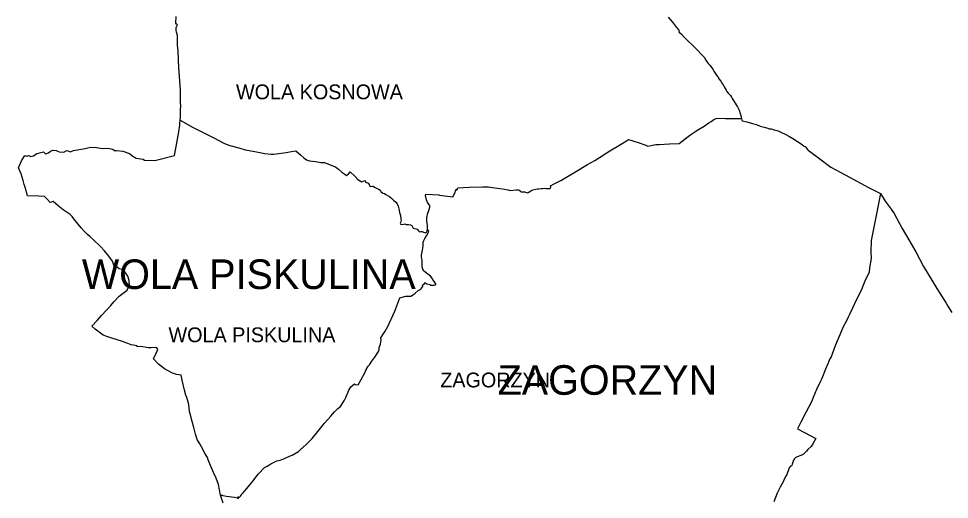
# Model space of a CAD drawing. Extents: x -562952 to -547638, y 190691 to 208158.
# Drawn here: x -562952 to -557283, y 202309 to 205234 of the extents above; entities that cross this region are included whole.
import ezdxf

# ---------------------------------------------------------------- set-up
doc = ezdxf.new("R2010")
doc.units = 0
for name, color, linetype in [('granica_gminy', 7, 'Continuous'), ('granica_sołectwa', 7, 'Continuous'), ('nazwy miejscowości', 7, 'Continuous'), ('nazwy miejscowości DUŻE', 7, 'Continuous'), ('obwódka', 7, 'Continuous')]:
    doc.layers.add(name, color=color, linetype=linetype)

msp = doc.modelspace()

# ---------------------------------------------------------------- linework, layer by layer
at = {"layer": 'granica_gminy'}
msp.add_lwpolyline([(-561705.3, 202285), (-561722.3, 202335.3), (-561733.8, 202399.5), (-561749, 202437.6), (-561764.1, 202472.4), (-561782.1, 202515.8), (-561796.6, 202549.2), (-561802.2, 202563.4), (-561815, 202586.5), (-561838, 202627.6), (-561848.7, 202645.8), (-561863.9, 202672.8), (-561873.8, 202706), (-561884.1, 202745.5), (-561894.5, 202783), (-561905.1, 202820.9), (-561911.2, 202843.6), (-561915, 202885.4), (-561927.8, 202927.9), (-561933.8, 202942.5), (-561940.7, 202972.5), (-561954.8, 203034.6), (-561961.9, 203063.8), (-561989.8, 203068.2), (-562015, 203075.6), (-562063.8, 203102.5), (-562099.8, 203130.4), (-562130.2, 203162.8), (-562113.1, 203199.1), (-562103, 203219.9), (-562109.4, 203229.8), (-562118.6, 203232.3), (-562143.8, 203230.8), (-562160.4, 203231.3), (-562206.5, 203238.1), (-562228.8, 203236.9), (-562230.3, 203241.9), (-562266.8, 203248.5), (-562287.5, 203257.4), (-562318.7, 203269.6), (-562383.2, 203288.8), (-562414.9, 203299.2), (-562436.4, 203307.1), (-562484.8, 203344.9), (-562504.9, 203362.5), (-562473.2, 203397.3), (-562446, 203427.7), (-562414.9, 203462.1), (-562390.6, 203488.6), (-562371.3, 203510.4), (-562340.2, 203545), (-562291, 203581.6), (-562276.9, 203611.7), (-562277.6, 203634.7), (-562279.3, 203639.9), (-562285.8, 203666.8), (-562299.9, 203688), (-562308.5, 203698.9), (-562313.1, 203702.6), (-562321.8, 203706.8), (-562338.9, 203712), (-562351.2, 203721.7), (-562370, 203728.4), (-562380.2, 203759), (-562402.2, 203787.7), (-562428.3, 203820.4), (-562454.3, 203849.9), (-562493.8, 203885.7), (-562515.5, 203905.7), (-562531.9, 203920.1), (-562554.3, 203943.2), (-562571.4, 203960.6), (-562606.7, 204005), (-562622.3, 204024.1), (-562625, 204030), (-562638.1, 204041.3), (-562679.8, 204070), (-562710.8, 204095.5), (-562740.6, 204120.2), (-562758.7, 204114.3), (-562778.9, 204135.3), (-562793.5, 204152), (-562827.9, 204153.8), (-562898.1, 204156.5), (-562911.5, 204208.4), (-562918.2, 204225), (-562924.6, 204248), (-562936.7, 204289.2), (-562951.8, 204325.3), (-562934, 204369), (-562913, 204399.9), (-562908.5, 204399.7), (-562899.1, 204396.5), (-562892.5, 204401.2), (-562884, 204398.4), (-562878.1, 204394.2), (-562861.3, 204399.2), (-562839.9, 204414), (-562833.5, 204415.3), (-562800.1, 204422.4), (-562794.9, 204417), (-562787.9, 204410.3), (-562769.2, 204417), (-562758.6, 204428.1), (-562740.5, 204433.6), (-562723, 204432.3), (-562703.9, 204423.2), (-562676.1, 204421.2), (-562659, 204430.4), (-562636, 204422.2), (-562617.5, 204431.1), (-562546.1, 204442.7), (-562522.6, 204450.4), (-562490, 204450.7), (-562441.8, 204444), (-562408.7, 204444.5), (-562377.3, 204439), (-562367.4, 204431.4), (-562356.3, 204430.4), (-562316.7, 204427.4), (-562277.2, 204414), (-562263.8, 204403.1), (-562255.2, 204396.5), (-562236.4, 204385.6), (-562192.8, 204378.2), (-562184.9, 204373.2), (-562122.1, 204369.5), (-562001.4, 204400.2), (-561992.5, 204456.5), (-561976.1, 204544.6), (-561970.5, 204585.8), (-561969.7, 204596.2), (-561967.1, 204615.2), (-561965.7, 204630.7), (-561965.9, 204679.8), (-561964.8, 204700.1), (-561965.6, 204724.1), (-561965.9, 204744.5), (-561965.6, 204800.7), (-561976.8, 204934.1), (-561981, 205035.6), (-561983.2, 205071.8), (-561983.8, 205131.9), (-561989.2, 205151.8), (-561992, 205164.3), (-561991.4, 205179.4), (-561984.5, 205196.8), (-561990.5, 205200.1), (-561995, 205205.5), (-561993.1, 205247.4)], dxfattribs=at)
at = {"layer": 'granica_sołectwa'}
for p, q in [((-559285.8, 204468.2), (-559248.5, 204490.9)), ((-559248.5, 204490.9), (-559236.3, 204498.3)), ((-559236.3, 204498.3), (-559179.2, 204479.4)), ((-558929, 204474.6), (-558874.4, 204515.5)), ((-558874.4, 204515.5), (-558857.9, 204527.9)), ((-559442.9, 204371.2), (-559351, 204428.3)), ((-559351, 204428.3), (-559285.8, 204468.2)), ((-559179.2, 204479.4), (-559132.2, 204463.1)), ((-559132.2, 204463.1), (-559118.7, 204458.6)), ((-559118.7, 204458.6), (-559070.5, 204466.9)), ((-559070.5, 204466.9), (-559050.8, 204468.5)), ((-559050.8, 204468.5), (-558986.5, 204471.7)), ((-558986.5, 204471.7), (-558929, 204474.6)), ((-559486.4, 204345.9), (-559442.9, 204371.2)), ((-559565, 204299.3), (-559486.4, 204345.9)), ((-559648.7, 204249.4), (-559565, 204299.3)), ((-560281.4, 204192.5), (-560277, 204204.3)), ((-560277, 204204.3), (-560242.8, 204205.8)), ((-560125.9, 204210.4), (-560090.7, 204210.7)), ((-560090.7, 204210.7), (-560064.9, 204206.3)), ((-560064.9, 204206.3), (-560004, 204198)), ((-560004, 204198), (-559969.5, 204192.4)), ((-559801.9, 204196.5), (-559792, 204197.8)), ((-559792, 204197.8), (-559783.3, 204198.2)), ((-559783.3, 204198.2), (-559769.5, 204200.7)), ((-559769.5, 204200.7), (-559761, 204200.6)), ((-559761, 204200.6), (-559748.6, 204201.3)), ((-559748.6, 204201.3), (-559739, 204200.8)), ((-559724, 204199.5), (-559715.5, 204200.2)), ((-559711.8, 204216), (-559689.6, 204228)), ((-559710.6, 204210.7), (-559711.8, 204216)), ((-559689.6, 204228), (-559648.7, 204249.4)), ((-560473.3, 204157.3), (-560471.1, 204164.7)), ((-560467.3, 204131.2), (-560473.3, 204157.3)), ((-560471.1, 204164.7), (-560392.9, 204161.9)), ((-560307.5, 204148.6), (-560297.5, 204167.6)), ((-560297.5, 204167.6), (-560286.7, 204195.6)), ((-560286.7, 204195.6), (-560281.4, 204192.5)), ((-559969.5, 204192.4), (-559962.4, 204187.6)), ((-559962.4, 204187.6), (-559918.4, 204192.3)), ((-559918.4, 204192.3), (-559906.5, 204192.5)), ((-559906.5, 204192.5), (-559899.6, 204189.4)), ((-559899.6, 204189.4), (-559900, 204183.5)), ((-559900, 204183.5), (-559890.9, 204180.2)), ((-559890.9, 204180.2), (-559878, 204180.3)), ((-559878, 204180.3), (-559870.6, 204179.4)), ((-559870.6, 204179.4), (-559852.2, 204173.8)), ((-559852.2, 204173.8), (-559847.4, 204174.9)), ((-559847.4, 204174.9), (-559832.2, 204185.9)), ((-559832.2, 204185.9), (-559819.2, 204191.4)), ((-559819.2, 204191.4), (-559801.9, 204196.5)), ((-557703, 204169.3), (-557727.2, 204045.3)), ((-560464.4, 204120.4), (-560467.3, 204131.2)), ((-560462.9, 204116.8), (-560464.4, 204120.4)), ((-560459.6, 204112), (-560462.9, 204116.8)), ((-560455.4, 204107.7), (-560459.6, 204112)), ((-560450.5, 204101.1), (-560455.4, 204107.7)), ((-560447.7, 204096.1), (-560450.5, 204101.1)), ((-560450.4, 204071.9), (-560446.4, 204086.1)), ((-560446.4, 204090.6), (-560447.7, 204096.1)), ((-560446.4, 204086.1), (-560446.4, 204090.6)), ((-560465.8, 204023.5), (-560464.4, 204032.3)), ((-560464.4, 204032.3), (-560461.1, 204044.9)), ((-560461.1, 204044.9), (-560459.9, 204050.4)), ((-560459.9, 204050.4), (-560454.6, 204059.4)), ((-560454.6, 204059.4), (-560450.4, 204071.9)), ((-560465.8, 204015.9), (-560465.8, 204023.5)), ((-560465.1, 204003.5), (-560465.8, 204015.9)), ((-560464.4, 203989.6), (-560465.1, 204003.5)), ((-560462.4, 203975.8), (-560464.4, 203989.6)), ((-560461, 203961.8), (-560462.4, 203975.8)), ((-560462.4, 203949.9), (-560461, 203961.8)), ((-560493, 203758.4), (-560494.4, 203764.8)), ((-560493.6, 203741.5), (-560493, 203758.4)), ((-560493.6, 203724.2), (-560493.6, 203741.5)), ((-560489.1, 203709.2), (-560493.6, 203724.2)), ((-560483.5, 203699.8), (-560489.1, 203709.2)), ((-560477.3, 203693.3), (-560483.5, 203699.8)), ((-560459.1, 203678.4), (-560477.3, 203693.3)), ((-560443.8, 203666), (-560459.1, 203678.4)), ((-560434.4, 203657.2), (-560443.8, 203666)), ((-560424.3, 203640.7), (-560434.4, 203657.2)), ((-560409, 203616.3), (-560424.3, 203640.7)), ((-560537.2, 203564.2), (-560517.7, 203578.8)), ((-560517.7, 203578.8), (-560501.4, 203588)), ((-560501.4, 203588), (-560490.7, 203604.6)), ((-560491.7, 203612.4), (-560479.9, 203622.8)), ((-560490.7, 203604.6), (-560491.7, 203612.4)), ((-560479.9, 203622.8), (-560476.7, 203628)), ((-560476.7, 203628), (-560465, 203620.9)), ((-560465, 203620.9), (-560447.7, 203615.7)), ((-560447.7, 203615.7), (-560440.5, 203611.1)), ((-560440.5, 203611.1), (-560421.3, 203611.1)), ((-560421.3, 203611.1), (-560409, 203616.3)), ((-560661.2, 203453.2), (-560630.3, 203534.7)), ((-560630.3, 203534.7), (-560593.8, 203544.4)), ((-560593.8, 203544.4), (-560562.6, 203545)), ((-560562.6, 203545), (-560546.7, 203554.4)), ((-560546.7, 203554.4), (-560537.2, 203564.2)), ((-560703.2, 203359.9), (-560661.2, 203453.2)), ((-560718.7, 203332.7), (-560703.2, 203359.9)), ((-560746.4, 203292), (-560737, 203303.4)), ((-560743.5, 203277.7), (-560746.4, 203292)), ((-560737, 203303.4), (-560732.1, 203314.8)), ((-560732.1, 203314.8), (-560718.7, 203332.7)), ((-560755.8, 203232.4), (-560751.6, 203243.5)), ((-560751.6, 203243.5), (-560748.7, 203252.6)), ((-560748.7, 203252.6), (-560743.5, 203277.7)), ((-560782.2, 203173.3), (-560759.4, 203208.1)), ((-560759.4, 203208.1), (-560756.8, 203217.9)), ((-560756.8, 203217.9), (-560755.8, 203232.4)), ((-560822.9, 203118.2), (-560815.4, 203126.7)), ((-560815.4, 203126.7), (-560799.5, 203148.9)), ((-560799.5, 203148.9), (-560782.2, 203173.3)), ((-560865.5, 203038.2), (-560843.3, 203079.2)), ((-560843.3, 203079.2), (-560834.9, 203099.8)), ((-560834.9, 203099.8), (-560822.9, 203118.2)), ((-560927.9, 202992.6), (-560906.2, 203012.1)), ((-560906.2, 203012.1), (-560902.6, 203008.2)), ((-560902.6, 203008.2), (-560883, 203005.3)), ((-560883, 203005.3), (-560865.5, 203038.2)), ((-560959.2, 202929.1), (-560940, 202972.7)), ((-560940, 202972.7), (-560927.9, 202992.6)), ((-560991.1, 202873.7), (-560966.7, 202911.8)), ((-560966.7, 202911.8), (-560959.2, 202929.1)), ((-561040.5, 202826.4), (-561027.5, 202840.7)), ((-561027.5, 202840.7), (-561007.3, 202861.6)), ((-561007.3, 202861.6), (-560991.1, 202873.7)), ((-561089, 202772.9), (-561067.5, 202794.8)), ((-561067.5, 202794.8), (-561049.6, 202815)), ((-561049.6, 202815), (-561040.5, 202826.4)), ((-561129.4, 202722.5), (-561089, 202772.9)), ((-561200.5, 202643.3), (-561163.5, 202679.3)), ((-561163.5, 202679.3), (-561129.4, 202722.5)), ((-561238.3, 202607.4), (-561200.5, 202643.3)), ((-561358.3, 202546.5), (-561335.8, 202555)), ((-561335.8, 202555), (-561301.1, 202572.3)), ((-561301.1, 202572.3), (-561286.2, 202578.4)), ((-561286.2, 202578.4), (-561247.4, 202600.3)), ((-561247.4, 202600.3), (-561238.3, 202607.4)), ((-561490.1, 202463.9), (-561454, 202503.7)), ((-561454, 202503.7), (-561437.7, 202510.9)), ((-561437.7, 202510.9), (-561428.3, 202516.2)), ((-561428.3, 202516.2), (-561415, 202524.7)), ((-561415, 202524.7), (-561398.4, 202532.8)), ((-561398.4, 202532.8), (-561379.2, 202544.2)), ((-561379.2, 202544.2), (-561369.4, 202544.9)), ((-561369.4, 202544.9), (-561358.3, 202546.5)), ((-561532.1, 202410.8), (-561499.2, 202454.5)), ((-561499.2, 202454.5), (-561490.1, 202463.9)), ((-561563.2, 202373.2), (-561532.1, 202410.8)), ((-561722.3, 202335.3), (-561710.9, 202333.7)), ((-561605.6, 202323.1), (-561601.3, 202327.6)), ((-561601.3, 202327.6), (-561595.5, 202334.1)), ((-561595.5, 202334.1), (-561589.3, 202342.9)), ((-561589.3, 202342.9), (-561583.8, 202349.4)), ((-561583.8, 202349.4), (-561563.2, 202373.2)), ((-561609.5, 202322), (-561605.6, 202323.1))]:
    msp.add_line(p, q, dxfattribs=at)
for points in [[(-558994.7, 205242.4), (-558970.1, 205211.2), (-558945.3, 205180.5), (-558931.5, 205162.8), (-558927.8, 205158.4), (-558930, 205153.9), (-558915.3, 205138.2), (-558898.7, 205121.6), (-558873.3, 205097.2), (-558850.9, 205075.8), (-558814.4, 205039.7), (-558794.2, 205017.6), (-558776, 204998.5), (-558765.8, 204981.8), (-558758.6, 204968.5), (-558752.2, 204960.2), (-558742.6, 204949.8), (-558730.3, 204934.1), (-558722.5, 204922.5), (-558716.6, 204913.2), (-558709.9, 204901.6), (-558701.1, 204888.6), (-558689.2, 204872.8), (-558687.9, 204867.9), (-558674.3, 204853.6), (-558665.8, 204839.7), (-558660.3, 204830.3), (-558655.5, 204819), (-558643.3, 204798.1), (-558638.5, 204790.8), (-558630.6, 204780.2), (-558616.3, 204765.3), (-558610.3, 204756.2), (-558606.3, 204747.4), (-558598.7, 204736.1), (-558580.5, 204708.8), (-558572.4, 204696), (-558563.9, 204676.5), (-558557.2, 204656.2), (-558551.8, 204635.5), (-558548.7, 204623.7), (-558546, 204615.2), (-558544.5, 204611), (-558516, 204605.8), (-558481.7, 204596.1), (-558456.6, 204588.5), (-558435.1, 204579.7), (-558410.8, 204573.4), (-558389, 204567), (-558380.2, 204563), (-558367.4, 204562.7), (-558350.5, 204557.6), (-558332.9, 204552.4), (-558325.6, 204550.3), (-558305.2, 204541.2), (-558282.3, 204530.1), (-558256.2, 204516.1), (-558235.9, 204503.6), (-558208.2, 204486.3), (-558185.8, 204471.2), (-558173.2, 204460.9), (-558168.9, 204457.6), (-558164.1, 204455.2), (-558161.3, 204455.5), (-558155.6, 204448.2), (-558147.4, 204437.9), (-558143.4, 204433.3), (-558126.7, 204421.2), (-558079.2, 204386.7), (-558004.3, 204330.6), (-557943.7, 204297.5), (-557864.9, 204254.8), (-557779.3, 204208.7), (-557703, 204169.3)], [(-561967.1, 204615.2), (-561892.8, 204574), (-561836, 204544.9), (-561763, 204508), (-561697.2, 204474.4), (-561666.1, 204461.9), (-561610.9, 204446.6), (-561572.8, 204436.2), (-561512.2, 204425.8), (-561452.6, 204412.6), (-561414, 204409.6), (-561396.7, 204408.8), (-561322.1, 204419.6), (-561288.9, 204425.8), (-561262.8, 204428.3), (-561233.9, 204402.7), (-561214, 204385.7), (-561197.4, 204374.5), (-561180.4, 204369.1), (-561143.5, 204365), (-561110.7, 204359.1), (-561088.9, 204358), (-561034.1, 204336.8), (-561020.9, 204331), (-561011.3, 204324.8), (-561003.9, 204318.1), (-560982.3, 204300.3), (-560965.3, 204286.6), (-560954.9, 204279.5), (-560941.2, 204290.7), (-560932.9, 204301.5), (-560902.7, 204273), (-560885.3, 204255.1), (-560861.3, 204241.4), (-560841.4, 204249.4), (-560839.9, 204241.6), (-560839.1, 204239.6), (-560821.2, 204232.7), (-560813.5, 204214.8), (-560809.9, 204212.1), (-560797.3, 204214.5), (-560791.4, 204214.3), (-560783.3, 204208.6), (-560768.8, 204200.7), (-560757, 204195.1), (-560750.4, 204190.4), (-560745.9, 204181.8), (-560734.1, 204172.2), (-560723.3, 204170), (-560714.2, 204162.6), (-560701.4, 204156.2), (-560693.8, 204151.8), (-560677.8, 204138.8), (-560667.5, 204129.7), (-560654, 204116.9), (-560646.2, 204106.6), (-560639.1, 204092.6), (-560635.9, 204076.8), (-560631.7, 204054), (-560626.5, 204035.9), (-560623.1, 204013.3), (-560620.9, 204004.7), (-560624.6, 203997.3), (-560627.8, 203989.9), (-560626.8, 203984.5), (-560624.3, 203982), (-560604.7, 203984), (-560599.5, 203984.2), (-560590.9, 203982), (-560577.4, 203982), (-560564.8, 203979.6), (-560557.7, 203974.6), (-560553.8, 203966), (-560549.2, 203959.5), (-560540.1, 203956.5), (-560531, 203954.1), (-560525.1, 203951.8), (-560521.2, 203947.9), (-560517, 203942.7), (-560512.3, 203938.3), (-560509.6, 203936.8), (-560502.5, 203938.6), (-560493.4, 203938.6), (-560485.3, 203934.6), (-560478.6, 203932.4), (-560471.3, 203930.2), (-560466.6, 203933.6), (-560464.4, 203943.2), (-560462.4, 203949.9)], [(-558857.9, 204527.9), (-558845.7, 204536.5), (-558821.1, 204552.7), (-558800, 204564.6), (-558776.3, 204580), (-558747.8, 204600.2), (-558734.1, 204607.7), (-558725.8, 204614.3), (-558717.4, 204620), (-558702.9, 204626.1), (-558689.3, 204628.8), (-558646.7, 204625.7), (-558594.9, 204625.7), (-558549.2, 204625.7)], [(-560242.8, 204205.8), (-560207.4, 204207.4), (-560125.9, 204210.4)], [(-559739, 204200.8), (-559731.8, 204199.2), (-559724, 204199.5)], [(-559715.5, 204200.2), (-559712.2, 204201.9), (-559710.6, 204210.7)], [(-560392.9, 204161.9), (-560388.2, 204160.5), (-560307.5, 204148.6)], [(-557703, 204169.3), (-557673, 204123.8), (-557638, 204074), (-557619.7, 204048.4), (-557570.1, 203957.5), (-557510.2, 203854.1), (-557488.1, 203814.6), (-557440.3, 203726), (-557389, 203642.5), (-557358.4, 203590.8), (-557331, 203547.1), (-557303, 203502.3), (-557291.4, 203484.1), (-557267.3, 203446.2)], [(-557727.2, 204045.3), (-557759.1, 203884), (-557761, 203814.9), (-557759.9, 203774.8), (-557768.9, 203716.7), (-557770.8, 203691.8), (-557796.8, 203635.6), (-557810, 203606.4), (-557820.6, 203580), (-557850, 203520.4), (-557872.6, 203472.7), (-557890.7, 203434.2), (-557898.6, 203416.8), (-557909.1, 203394.3), (-557926.8, 203362.7), (-557939.3, 203333.6), (-557978.1, 203243.3), (-557995.7, 203198), (-558003.3, 203176.5), (-558010, 203163.7), (-558022.9, 203133.5), (-558037.6, 203100.2), (-558060.2, 203044.8), (-558068.1, 203027), (-558092.6, 202977.6), (-558113, 202927.8), (-558123.1, 202903), (-558155.5, 202840.4), (-558187.3, 202778.5)], [(-560494.4, 203764.8), (-560495.9, 203771.8), (-560497.2, 203783.7), (-560498.5, 203797.4), (-560496.5, 203805.2), (-560492.3, 203824.4), (-560488.4, 203851.8), (-560487.7, 203872.6), (-560484.2, 203884.7), (-560478, 203895.8), (-560468.2, 203911.7), (-560458.4, 203926.1), (-560453.6, 203940.1), (-560462.4, 203949.9)], [(-558187.3, 202778.5), (-558207.6, 202738.6), (-558165.3, 202715.4), (-558096.8, 202679.7), (-558115.4, 202646.8), (-558125.4, 202630.3), (-558144.4, 202612.9), (-558153.5, 202601.5), (-558173.8, 202582.1), (-558187.9, 202576.7), (-558208.9, 202567.4), (-558218.8, 202562.6), (-558221.1, 202561.1), (-558224.8, 202558.1), (-558231.9, 202546.3), (-558239.1, 202530), (-558239.4, 202523.4), (-558241.5, 202515.1), (-558243.9, 202512.4), (-558252, 202508.5), (-558259.4, 202501.1), (-558261.5, 202493.9), (-558273.8, 202459.5), (-558278.6, 202449.6), (-558288.7, 202431.7), (-558293.9, 202418.9)], [(-558293.9, 202418.9), (-558313.2, 202383.8), (-558332.3, 202346.9), (-558352.7, 202293.1)], [(-561710.9, 202333.7), (-561707.3, 202333.2), (-561686.3, 202329.3), (-561669.7, 202325.6), (-561654.4, 202324.1), (-561637.6, 202321.3), (-561621.3, 202318.4), (-561613.3, 202314.4), (-561616.8, 202324.3), (-561613.8, 202323.6), (-561609.5, 202322)]]:
    msp.add_lwpolyline(points, dxfattribs=at)
at = {"layer": 'obwódka'}
msp.add_lwpolyline([(-561705.3, 202285), (-561722.3, 202335.3), (-561733.8, 202399.5), (-561749, 202437.6), (-561764.1, 202472.4), (-561782.1, 202515.8), (-561796.6, 202549.2), (-561802.2, 202563.4), (-561815, 202586.5), (-561838, 202627.6), (-561848.7, 202645.8), (-561863.9, 202672.8), (-561873.8, 202706), (-561884.1, 202745.5), (-561894.5, 202783), (-561905.1, 202820.9), (-561911.2, 202843.6), (-561915, 202885.4), (-561927.8, 202927.9), (-561933.8, 202942.5), (-561940.7, 202972.5), (-561954.8, 203034.6), (-561961.9, 203063.8), (-561989.8, 203068.2), (-562015, 203075.6), (-562063.8, 203102.5), (-562099.8, 203130.4), (-562130.2, 203162.8), (-562113.1, 203199.1), (-562103, 203219.9), (-562109.4, 203229.8), (-562118.6, 203232.3), (-562143.8, 203230.8), (-562160.4, 203231.3), (-562206.5, 203238.1), (-562228.8, 203236.9), (-562230.3, 203241.9), (-562266.8, 203248.5), (-562287.5, 203257.4), (-562318.7, 203269.6), (-562383.2, 203288.8), (-562414.9, 203299.2), (-562436.4, 203307.1), (-562484.8, 203344.9), (-562504.9, 203362.5), (-562473.2, 203397.3), (-562446, 203427.7), (-562414.9, 203462.1), (-562390.6, 203488.6), (-562371.3, 203510.4), (-562340.2, 203545), (-562291, 203581.6), (-562276.9, 203611.7), (-562277.6, 203634.7), (-562279.3, 203639.9), (-562285.8, 203666.8), (-562299.9, 203688), (-562308.5, 203698.9), (-562313.1, 203702.6), (-562321.8, 203706.8), (-562338.9, 203712), (-562351.2, 203721.7), (-562370, 203728.4), (-562380.2, 203759), (-562402.2, 203787.7), (-562428.3, 203820.4), (-562454.3, 203849.9), (-562493.8, 203885.7), (-562515.5, 203905.7), (-562531.9, 203920.1), (-562554.3, 203943.2), (-562571.4, 203960.6), (-562606.7, 204005), (-562622.3, 204024.1), (-562625, 204030), (-562638.1, 204041.3), (-562679.8, 204070), (-562710.8, 204095.5), (-562740.6, 204120.2), (-562758.7, 204114.3), (-562778.9, 204135.3), (-562793.5, 204152), (-562827.9, 204153.8), (-562898.1, 204156.5), (-562911.5, 204208.4), (-562918.2, 204225), (-562924.6, 204248), (-562936.7, 204289.2), (-562951.8, 204325.3), (-562934, 204369), (-562913, 204399.9), (-562908.5, 204399.7), (-562899.1, 204396.5), (-562892.5, 204401.2), (-562884, 204398.4), (-562878.1, 204394.2), (-562861.3, 204399.2), (-562839.9, 204414), (-562833.5, 204415.3), (-562800.1, 204422.4), (-562794.9, 204417), (-562787.9, 204410.3), (-562769.2, 204417), (-562758.6, 204428.1), (-562740.5, 204433.6), (-562723, 204432.3), (-562703.9, 204423.2), (-562676.1, 204421.2), (-562659, 204430.4), (-562636, 204422.2), (-562617.5, 204431.1), (-562546.1, 204442.7), (-562522.6, 204450.4), (-562490, 204450.7), (-562441.8, 204444), (-562408.7, 204444.5), (-562377.3, 204439), (-562367.4, 204431.4), (-562356.3, 204430.4), (-562316.7, 204427.4), (-562277.2, 204414), (-562263.8, 204403.1), (-562255.2, 204396.5), (-562236.4, 204385.6), (-562192.8, 204378.2), (-562184.9, 204373.2), (-562122.1, 204369.5), (-562001.4, 204400.2), (-561992.5, 204456.5), (-561976.1, 204544.6), (-561970.5, 204585.8), (-561969.7, 204596.2), (-561967.1, 204615.2), (-561965.7, 204630.7), (-561965.9, 204679.8), (-561964.8, 204700.1), (-561965.6, 204724.1), (-561965.9, 204744.5), (-561965.6, 204800.7), (-561976.8, 204934.1), (-561981, 205035.6), (-561983.2, 205071.8), (-561983.8, 205131.9), (-561989.2, 205151.8), (-561992, 205164.3), (-561991.4, 205179.4), (-561984.5, 205196.8), (-561990.5, 205200.1), (-561995, 205205.5), (-561993.1, 205247.4)], dxfattribs=at)

# ---------------------------------------------------------------- texts
at = {"layer": 'nazwy miejscowości'}
for s, p in [('WOLA KOSNOWA', (-561627.7, 204743)), ('WOLA PISKULINA', (-562038.9, 203265)), ('ZAGORZYN', (-560383.7, 202990.1))]:
    msp.add_text(s, height=90, dxfattribs=at).set_placement(p)
at = {"layer": 'nazwy miejscowości DUŻE'}
for s, p in [('WOLA PISKULINA', (-562566.5, 203588.6)), ('ZAGORZYN', (-560034.3, 202945.1))]:
    msp.add_text(s, height=180, dxfattribs=at).set_placement(p)

doc.saveas('drawing.dxf')
